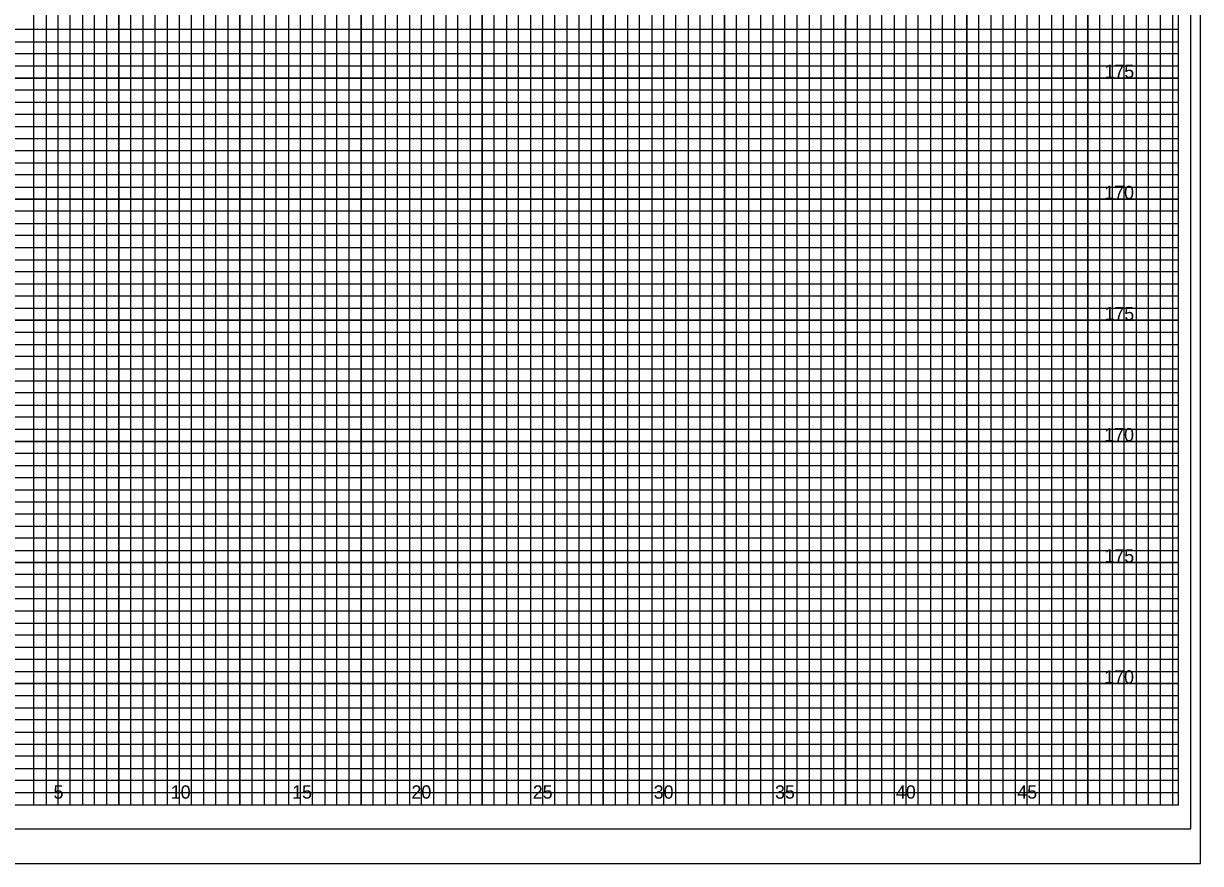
# Model space of a CAD drawing. Extents: x -4 to 103, y -2 to 209.
# Drawn here: x 54.82 to 103.4, y -2.43 to 32.25 of the extents above; entities that cross this region are included whole.
import ezdxf

# ---------------------------------------------------------------- set-up
doc = ezdxf.new("R2010")
doc.units = 0
for name, color, linetype in [('Prop XS Elevation Labels', 7, 'Continuous'), ('Prop XS Offset Labels', 7, 'Continuous'), ('Sheet Cross Section CELL', 7, 'Continuous'), ('Sheet Cross Section Grid Major CELL', 7, 'Continuous'), ('Sheet Cross Section Grid Middle CELL', 7, 'Continuous'), ('Sheet Cutting Line CELL', 7, 'Continuous'), ('Sheet DOT Grid CELL', 7, 'Continuous'), ('Sheet Plot Border Inside CELL', 7, 'Continuous'), ('Sheet Plot Border Outside CELL', 7, 'Continuous')]:
    doc.layers.add(name, color=color, linetype=linetype)

msp = doc.modelspace()

# ---------------------------------------------------------------- linework, layer by layer
at = {"layer": 'Sheet Cross Section CELL'}
msp.add_lwpolyline([(102.5, 65), (0, 65), (0, 0), (102.5, 0)], close=True, dxfattribs=at)
at = {"layer": 'Sheet Cross Section Grid Major CELL'}
for points in [[(56.25, 0), (56.25, 65)], [(58.75, 65), (58.75, 0), (61.25, 0), (61.25, 65)], [(63.75, 65), (63.75, 0), (66.25, 0), (66.25, 65)], [(68.75, 65), (68.75, 0), (71.25, 0), (71.25, 65)], [(73.75, 65), (73.75, 0), (76.25, 0), (76.25, 62)], [(88.75, 62), (88.75, 0), (91.25, 0), (91.25, 63.425)], [(93.75, 63.425), (93.75, 0), (96.25, 0), (96.25, 63.425)], [(98.75, 63.425), (98.75, 0), (101.25, 0), (101.25, 63.425)], [(78.75, 62), (78.75, 0), (81.25, 0), (81.25, 62)], [(83.75, 62), (83.75, 0), (86.25, 0), (86.25, 62)], [(0, 27.5), (102.5, 27.5), (102.5, 30), (0, 30)], [(0, 22.5), (102.5, 22.5), (102.5, 25), (0, 25)], [(0, 17.5), (102.5, 17.5), (102.5, 20), (0, 20)], [(0, 12.5), (102.5, 12.5), (102.5, 15), (0, 15)], [(0, 7.5), (102.5, 7.5), (102.5, 10), (0, 10)], [(0, 2.5), (102.5, 2.5), (102.5, 5), (0, 5)]]:
    msp.add_lwpolyline(points, dxfattribs=at)
at = {"layer": 'Sheet Cross Section Grid Middle CELL'}
for points in [[(54.75, 0), (55.25, 0), (55.25, 65)], [(55.75, 65), (55.75, 0), (56.75, 0), (56.75, 65)], [(57.25, 65), (57.25, 0), (57.75, 0), (57.75, 65)], [(58.25, 65), (58.25, 0), (59.25, 0), (59.25, 65)], [(59.75, 65), (59.75, 0), (60.25, 0), (60.25, 65)], [(60.75, 65), (60.75, 0), (61.75, 0), (61.75, 65)], [(62.25, 65), (62.25, 0), (62.75, 0), (62.75, 65)], [(63.25, 65), (63.25, 0), (64.25, 0), (64.25, 65)], [(64.75, 65), (64.75, 0), (65.25, 0), (65.25, 65)], [(65.75, 65), (65.75, 0), (66.75, 0), (66.75, 65)], [(67.25, 65), (67.25, 0), (67.75, 0), (67.75, 65)], [(68.25, 65), (68.25, 0), (69.25, 0), (69.25, 65)], [(69.75, 65), (69.75, 0), (70.25, 0), (70.25, 65)], [(70.75, 65), (70.75, 0), (71.75, 0), (71.75, 65)], [(72.25, 65), (72.25, 0), (72.75, 0), (72.75, 65)], [(73.25, 65), (73.25, 0), (74.25, 0), (74.25, 62)], [(89.75, 62), (89.75, 0), (90.25, 0), (90.25, 63.425)], [(90.75, 63.425), (90.75, 0), (91.75, 0), (91.75, 63.425)], [(92.25, 63.425), (92.25, 0), (92.75, 0), (92.75, 63.425)], [(93.25, 63.425), (93.25, 0), (94.25, 0), (94.25, 63.425)], [(94.75, 63.425), (94.75, 0), (95.25, 0), (95.25, 63.425)], [(95.75, 63.425), (95.75, 0), (96.75, 0), (96.75, 63.425)], [(97.25, 63.425), (97.25, 0), (97.75, 0), (97.75, 63.425)], [(98.25, 63.425), (98.25, 0), (99.25, 0), (99.25, 63.425)], [(99.75, 63.425), (99.75, 0), (100.25, 0), (100.25, 63.425)], [(100.25, 63.425), (100.75, 63.425), (100.75, 0), (101.75, 0), (101.75, 63.425), (102.25, 63.425), (102.25, 0)], [(74.75, 62), (74.75, 0), (75.25, 0), (75.25, 62)], [(75.75, 62), (75.75, 0), (76.75, 0), (76.75, 62)], [(77.25, 62), (77.25, 0), (77.75, 0), (77.75, 62)], [(78.25, 62), (78.25, 0), (79.25, 0), (79.25, 62)], [(79.75, 62), (79.75, 0), (80.25, 0), (80.25, 62)], [(80.75, 62), (80.75, 0), (81.75, 0), (81.75, 62)], [(82.25, 62), (82.25, 0), (82.75, 0), (82.75, 62)], [(83.25, 62), (83.25, 0), (84.25, 0), (84.25, 62)], [(84.75, 62), (84.75, 0), (85.25, 0), (85.25, 62)], [(85.75, 62), (85.75, 0), (86.75, 0), (86.75, 62)], [(87.25, 62), (87.25, 0), (87.75, 0), (87.75, 62)], [(88.25, 62), (88.25, 0), (89.25, 0), (89.25, 62)], [(0, 31.5), (102.5, 31.5), (102.5, 32), (0, 32)], [(0, 30.5), (102.5, 30.5), (102.5, 31), (0, 31)], [(0, 29), (102.5, 29), (102.5, 29.5), (0, 29.5)], [(0, 28), (102.5, 28), (102.5, 28.5), (0, 28.5)], [(0, 26.5), (102.5, 26.5), (102.5, 27), (0, 27)], [(0, 25.5), (102.5, 25.5), (102.5, 26), (0, 26)], [(0, 24), (102.5, 24), (102.5, 24.5), (0, 24.5)], [(0, 23), (102.5, 23), (102.5, 23.5), (0, 23.5)], [(0, 21.5), (102.5, 21.5), (102.5, 22), (0, 22)], [(0, 20.5), (102.5, 20.5), (102.5, 21), (0, 21)], [(0, 19), (102.5, 19), (102.5, 19.5), (0, 19.5)], [(0, 18), (102.5, 18), (102.5, 18.5), (0, 18.5)], [(0, 16.5), (102.5, 16.5), (102.5, 17), (0, 17)], [(0, 15.5), (102.5, 15.5), (102.5, 16), (0, 16)], [(0, 14), (102.5, 14), (102.5, 14.5), (0, 14.5)], [(0, 13), (102.5, 13), (102.5, 13.5), (0, 13.5)], [(0, 11.5), (102.5, 11.5), (102.5, 12), (0, 12)], [(0, 10.5), (102.5, 10.5), (102.5, 11), (0, 11)], [(0, 9), (102.5, 9), (102.5, 9.5), (0, 9.5)], [(0, 8), (102.5, 8), (102.5, 8.5), (0, 8.5)], [(0, 6.5), (102.5, 6.5), (102.5, 7), (0, 7)], [(0, 5.5), (102.5, 5.5), (102.5, 6), (0, 6)], [(0, 4), (102.5, 4), (102.5, 4.5), (0, 4.5)], [(0, 3), (102.5, 3), (102.5, 3.5), (0, 3.5)], [(0, 1.5), (102.5, 1.5), (102.5, 2), (0, 2)], [(0, 0.5), (102.5, 0.5), (102.5, 1), (0, 1)]]:
    msp.add_lwpolyline(points, dxfattribs=at)
at = {"layer": 'Sheet Cutting Line CELL'}
msp.add_line((-3.5, -2.425), (103.4, -2.425), dxfattribs=at)
at = {"layer": 'Sheet DOT Grid CELL'}
for p, q in [((56.25, 0), (56.25, 65)), ((58.75, 0), (58.75, 65)), ((61.25, 0), (61.25, 65)), ((63.75, 0), (63.75, 65)), ((66.25, 0), (66.25, 65)), ((68.75, 0), (68.75, 65)), ((71.25, 0), (71.25, 65)), ((73.75, 0), (73.75, 65)), ((91.25, 0), (91.25, 63.425)), ((93.75, 0), (93.75, 63.425)), ((96.25, 0), (96.25, 63.425)), ((98.75, 0), (98.75, 63.425)), ((101.25, 0), (101.25, 63.425)), ((76.25, 0), (76.25, 62)), ((78.75, 0), (78.75, 62)), ((81.25, 0), (81.25, 62)), ((83.75, 0), (83.75, 62)), ((86.25, 0), (86.25, 62)), ((88.75, 0), (88.75, 62)), ((0, 30), (102.5, 30)), ((0, 27.5), (102.5, 27.5)), ((0, 25), (102.5, 25)), ((0, 22.5), (102.5, 22.5)), ((0, 20), (102.5, 20)), ((0, 17.5), (102.5, 17.5)), ((0, 15), (102.5, 15)), ((0, 12.5), (102.5, 12.5)), ((0, 10), (102.5, 10)), ((0, 7.5), (102.5, 7.5)), ((0, 5), (102.5, 5)), ((0, 2.5), (102.5, 2.5))]:
    msp.add_line(p, q, dxfattribs=at)
at = {"layer": 'Sheet Plot Border Inside CELL'}
msp.add_lwpolyline([(103, 66), (-2.8, 66), (-2.8, -1), (103, -1)], close=True, dxfattribs=at)
at = {"layer": 'Sheet Plot Border Outside CELL'}
msp.add_lwpolyline([(103.4, 67.4), (-3.5, 67.4), (-3.5, -2.425), (103.4, -2.425)], close=True, dxfattribs=at)

# ---------------------------------------------------------------- texts
at = {"layer": 'Prop XS Elevation Labels'}
for s, p in [('175', (99.43825, 30)), ('170', (99.42958, 25)), ('175', (99.43825, 20)), ('170', (99.42958, 15)), ('175', (99.43825, 10)), ('170', (99.42958, 5))]:
    msp.add_text(s, height=0.55, dxfattribs=at).set_placement(p)
at = {"layer": 'Prop XS Offset Labels'}
for s, p in [('5', (56.05742, 0.25)), ('10', (60.89708, 0.25)), ('15', (65.90575, 0.25)), ('20', (70.83125, 0.25)), ('25', (75.83992, 0.25)), ('30', (80.83125, 0.25)), ('35', (85.83992, 0.25)), ('40', (90.83125, 0.25)), ('45', (95.83992, 0.25))]:
    msp.add_text(s, height=0.55, dxfattribs=at).set_placement(p)

doc.saveas('drawing.dxf')
